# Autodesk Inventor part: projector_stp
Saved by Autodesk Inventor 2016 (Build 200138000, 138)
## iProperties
Created: 2016-03
Part Number: projector_stp
Material: Generic
Document SubType Name: Modeling
Designer: bongo_000
Density: 1 g/cm^3
Appearance: Default
Author: bongo_000
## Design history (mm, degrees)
feature "SOLID33"
feature "SOLID31"
feature "SOLID29"
feature "SOLID27"
feature "SOLID25"
feature "SOLID22"
feature "SOLID19"
feature "SOLID18"
feature "SOLID5:1"
feature "SOLID15"
feature "SOLID3:1"
feature "SOLID2:1"
feature "SOLID6:1"
feature "SOLID10:1"
feature "SOLID9:1"
feature "SOLID7:1"
feature "SOLID14:1"
feature "SOLID11:1"
feature "SOLID71"
feature "SOLID69"
feature "SOLID41"
feature "SOLID37"
feature "SOLID35"
body "Solid1"
body "Solid2"
body "Solid3"
body "Solid4"
body "Solid5"
body "Solid6"
body "Solid7"
body "Solid8"
body "Solid9"
body "Solid10"
body "Solid11"
body "Solid12"
body "Solid13"
body "Solid14"
body "Solid15"
body "Solid16"
body "Solid17"
body "Solid18"
body "Solid19"
body "Solid20"
body "Solid21"
body "Solid22"
body "Solid23"
